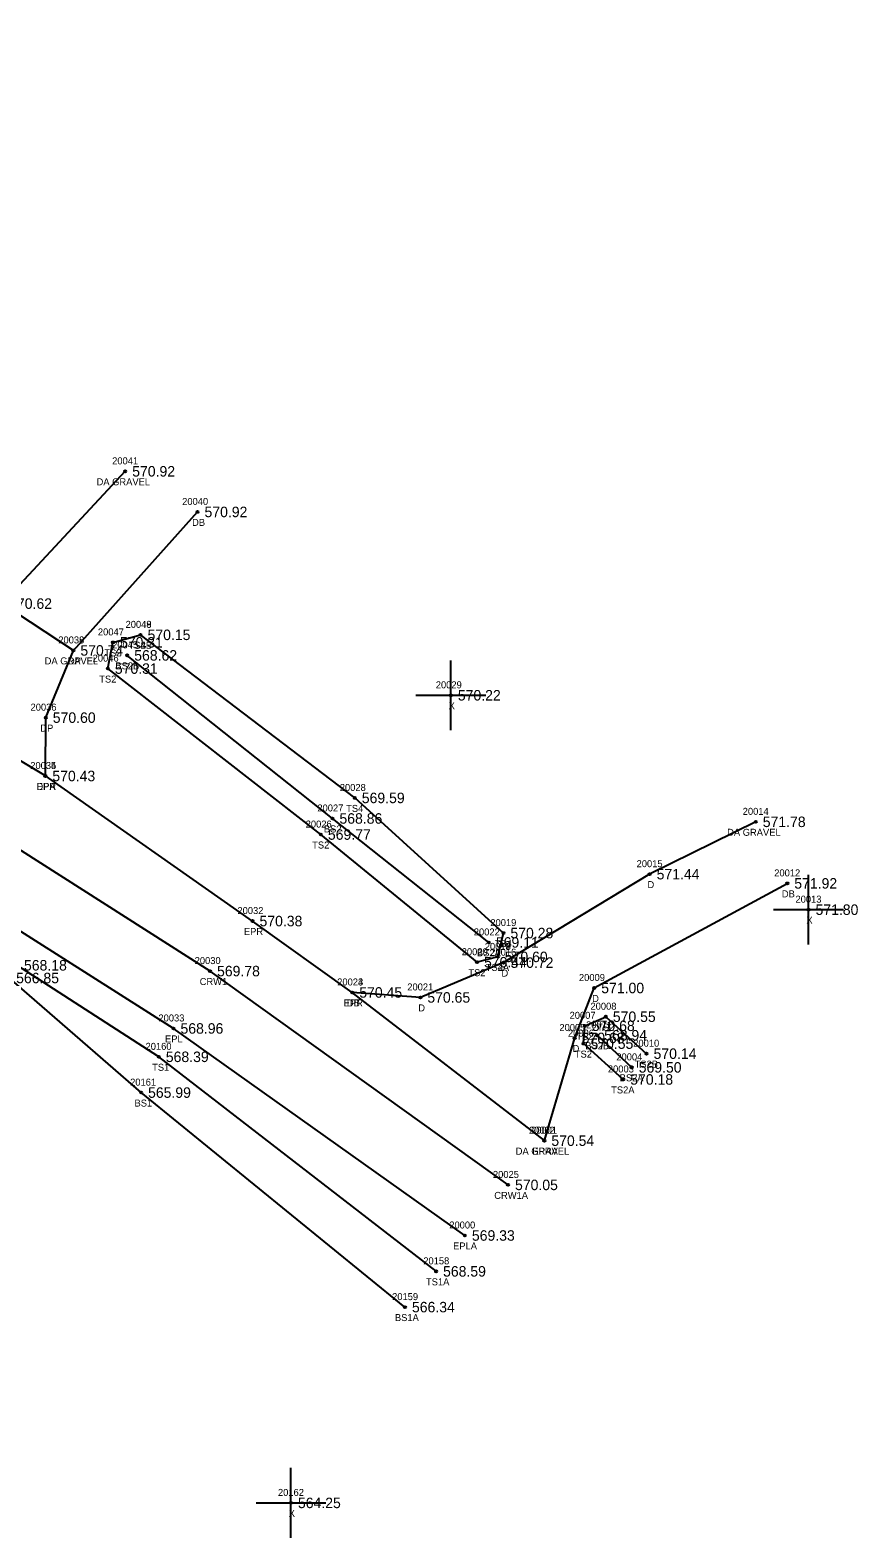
# Model space of a CAD drawing. Extents: x 1530159 to 1531652, y 877045 to 877724.
# Drawn here: x 1531533 to 1531651.5, y 877077 to 877292.8 of the extents above; entities that cross this region are included whole.
import ezdxf

# ---------------------------------------------------------------- set-up
doc = ezdxf.new("R2010")
doc.units = 0
for name, color, linetype in [('RD_DTM_BkLn1', 7, 'Continuous'), ('RD_DTM_BkLn2', 7, 'Continuous'), ('RD_DTM_BkLn_txCode', 7, 'Continuous'), ('RD_EX_Driveway', 7, 'Continuous'), ('RD_EX_Driveway_txCode', 7, 'Continuous'), ('RD_EX_Misc', 7, 'Continuous'), ('RD_EX_Misc_txCode', 7, 'Continuous'), ('RD_EX_Road', 7, 'Continuous'), ('RD_EX_Road_txCode', 7, 'Continuous'), ('RD_EX_TX_Driveway_ELEV', 7, 'Continuous'), ('RD_EX_TX_Misc_ELEV', 7, 'Continuous'), ('RD_EX_TX_Road_ELEV', 7, 'Continuous'), ('RD_HC_Survey_ELEV', 7, 'Continuous'), ('RD_HC_Survey_txCode', 7, 'Continuous'), ('RD_SMD_Locator', 7, 'Continuous')]:
    doc.layers.add(name, color=color, linetype=linetype)

msp = doc.modelspace()

# ---------------------------------------------------------------- linework, layer by layer
at = {"layer": 'RD_DTM_BkLn1'}
msp.add_lwpolyline([(1531601.44, 877127.51), (1531558.79, 877158.11), (1531516.37, 877185.16), (1531470.77, 877211.58), (1531426.8, 877229.22), (1531379.86, 877245.66), (1531330.99, 877260.09), (1531284.24, 877270.97), (1531236.44, 877276.73), (1531185.96, 877281.19), (1531132.29, 877281.48), (1531081.11, 877280.78), (1531028.25, 877278.4), (1530978.85, 877276.13), (1530941.18, 877274.78)], dxfattribs=at)
at = {"layer": 'RD_DTM_BkLn2'}
msp.add_line((1531619.14, 877144.33), (1531614.2, 877148.92), dxfattribs=at)
for points in [[(1531591.14, 877115.14), (1531551.46, 877145.84), (1531531.16, 877158.94), (1531508.8, 877174.74), (1531464.68, 877197.55), (1531424.35, 877215.57), (1531374.79, 877230.73), (1531373.87, 877227.7), (1531395.15, 877220.58)], [(1531586.69, 877110.02), (1531548.92, 877140.72), (1531530.04, 877157.12), (1531505.77, 877171.31), (1531462.4, 877192.61), (1531421.83, 877211.77), (1531413.77, 877214.99), (1531376.63, 877228.45)], [(1531599.98, 877160.14), (1531597, 877159.38), (1531574.66, 877177.65), (1531544.17, 877201.4), (1531544.9, 877205.15), (1531548.85, 877206.23)], [(1531599.98, 877160.14), (1531600.78, 877163.55), (1531579.51, 877182.89), (1531548.85, 877206.23)], [(1531598.7, 877162.21), (1531576.31, 877179.95), (1531546.94, 877203.29)], [(1531617.93, 877142.6), (1531612.24, 877147.73), (1531612.44, 877150.28), (1531615.44, 877151.58), (1531621.27, 877146.29)]]:
    msp.add_lwpolyline(points, dxfattribs=at)
at = {"layer": 'RD_EX_Driveway'}
for p, q in [((1531546.65, 877229.63), (1531529.04, 877210.7)), ((1531539.23, 877204), (1531557, 877223.82))]:
    msp.add_line(p, q, dxfattribs=at)
for points in [[(1531535.22, 877186.03), (1531535.28, 877194.38), (1531539.23, 877204), (1531529.04, 877210.7), (1531521.57, 877203.29), (1531511.53, 877200.27)], [(1531636.9, 877179.47), (1531621.71, 877171.98), (1531600.8, 877159.32), (1531588.89, 877154.34), (1531579.15, 877155.05)], [(1531606.64, 877133.84), (1531610.98, 877148.54), (1531613.78, 877155.69), (1531641.41, 877170.66)]]:
    msp.add_lwpolyline(points, dxfattribs=at)
at = {"layer": 'RD_EX_Misc'}
for p, q in [((1531593.26, 877192.58), (1531593.26, 877202.58)), ((1531588.26, 877197.58), (1531598.26, 877197.58)), ((1531644.45, 877161.9), (1531644.45, 877171.9)), ((1531639.45, 877166.9), (1531649.45, 877166.9)), ((1531570.37, 877077), (1531570.37, 877087)), ((1531565.37, 877082), (1531575.37, 877082))]:
    msp.add_line(p, q, dxfattribs=at)
at = {"layer": 'RD_EX_Road'}
for points in [[(1531606.64, 877133.84), (1531579.15, 877155.05), (1531564.87, 877165.27), (1531535.22, 877186.03), (1531511.53, 877200.27), (1531474.57, 877218.9), (1531430.45, 877239.35), (1531404.48, 877249.38), (1531382.32, 877256.43), (1531333.23, 877270.71), (1531303.67, 877277.44), (1531276.52, 877282.71), (1531237.32, 877287.2), (1531185.8, 877290.94), (1531132.61, 877292.77), (1531081.11, 877292.38), (1531038.69, 877288.67), (1530976.42, 877285.45), (1530941.06, 877284.26)], [(1531595.27, 877120.27), (1531553.56, 877149.9), (1531509.97, 877177.57), (1531465.94, 877201.73), (1531423.65, 877222), (1531376.09, 877237.68), (1531328.84, 877252.31), (1531282.81, 877261.85), (1531235.7, 877268.49), (1531185.47, 877272.84), (1531132.72, 877273.12), (1531080.2, 877271.87), (1531029.21, 877269.53), (1530978.47, 877268.32), (1530945.95, 877265.93), (1530941.45, 877262.44)]]:
    msp.add_lwpolyline(points, dxfattribs=at)
at = {"layer": 'RD_SMD_Locator'}
for centre in [(1531546.65, 877229.63), (1531557, 877223.82), (1531544.9, 877205.15), (1531548.85, 877206.23), (1531548.85, 877206.23), (1531539.23, 877204), (1531539.23, 877204), (1531546.94, 877203.29), (1531544.17, 877201.4), (1531593.26, 877197.58), (1531535.28, 877194.38), (1531535.22, 877186.03), (1531535.22, 877186.03), (1531579.51, 877182.89), (1531576.31, 877179.95), (1531636.9, 877179.47), (1531574.66, 877177.65), (1531621.71, 877171.98), (1531641.41, 877170.66), (1531644.45, 877166.9), (1531564.87, 877165.27), (1531600.78, 877163.55), (1531598.7, 877162.21), (1531597, 877159.38), (1531599.98, 877160.14), (1531599.98, 877160.14), (1531600.8, 877159.32), (1531558.79, 877158.11), (1531579.15, 877155.05), (1531579.15, 877155.05), (1531613.78, 877155.69), (1531588.89, 877154.34), (1531615.44, 877151.58), (1531553.56, 877149.9), (1531610.98, 877148.54), (1531612.44, 877150.28), (1531614.2, 877148.92), (1531612.24, 877147.73), (1531621.27, 877146.29), (1531551.46, 877145.84), (1531619.14, 877144.33), (1531617.93, 877142.6), (1531548.92, 877140.72), (1531606.64, 877133.84), (1531606.64, 877133.84), (1531601.44, 877127.51), (1531595.27, 877120.27), (1531591.14, 877115.14), (1531586.69, 877110.02), (1531570.37, 877082)]:
    msp.add_circle(centre, 0.15, dxfattribs=at)

# ---------------------------------------------------------------- texts
at = {"layer": 'RD_DTM_BkLn_txCode'}
for s, p in [('20047', (1531542.74, 877206.15)), ('20048', (1531546.7, 877207.23)), ('20049', (1531546.7, 877207.23)), ('20045', (1531544.78, 877204.29)), ('TS2B', (1531547.14, 877204.23)), ('TS4B', (1531547.14, 877204.23)), ('20046', (1531541.99, 877202.4)), ('TS2', (1531543.66, 877203.15)), ('TS2', (1531542.93, 877199.4)), ('BS2B', (1531545.24, 877201.29)), ('20028', (1531577.36, 877183.89)), ('20027', (1531574.15, 877180.95)), ('TS4', (1531578.27, 877180.89)), ('20026', (1531572.48, 877178.65)), ('BS2', (1531575.08, 877177.95)), ('TS2', (1531573.41, 877175.65)), ('20022', (1531596.54, 877163.21)), ('20019', (1531598.91, 877164.55)), ('20017', (1531598.11, 877161.14)), ('20018', (1531598.11, 877161.14)), ('TS4', (1531599.54, 877161.55)), ('20020', (1531594.81, 877160.38)), ('BS2A', (1531596.98, 877160.21)), ('TS2', (1531595.76, 877157.38)), ('TS2A', (1531598.25, 877158.14)), ('TS4A', (1531598.25, 877158.14)), ('20008', (1531613.24, 877152.58)), ('20007', (1531610.25, 877151.28)), ('20011', (1531612.61, 877149.92)), ('20006', (1531610.02, 877148.73)), ('TS2', (1531611.2, 877148.28)), ('TS2', (1531614.2, 877149.58)), ('20160', (1531549.56, 877146.84)), ('TS2', (1531611, 877145.73)), ('BS2B', (1531612.5, 877146.92)), ('20010', (1531619.36, 877147.29)), ('TS1', (1531550.5, 877143.84)), ('20003', (1531615.73, 877143.6)), ('20004', (1531616.94, 877145.33)), ('TS2B', (1531619.56, 877144.29)), ('20161', (1531547.35, 877141.72)), ('BS2A', (1531617.42, 877142.33)), ('TS2A', (1531616.2, 877140.6)), ('BS1', (1531547.98, 877138.72)), ('20158', (1531589.31, 877116.14)), ('TS1A', (1531589.7, 877113.14)), ('20159', (1531584.85, 877111.02)), ('BS1A', (1531585.25, 877108.02))]:
    msp.add_text(s, height=1, dxfattribs=at).set_placement(p)
at = {"layer": 'RD_EX_Driveway_txCode'}
for s, p in [('20041', (1531544.78, 877230.63)), ('DA GRAVEL', (1531542.55, 877227.63)), ('20040', (1531554.8, 877224.82)), ('DB', (1531556.22, 877221.82)), ('20038', (1531537.07, 877205)), ('20039', (1531537.07, 877205)), ('DA GRAVEL', (1531535.12, 877202)), ('DP', (1531538.45, 877202)), ('20036', (1531533.1, 877195.38)), ('DP', (1531534.5, 877192.38)), ('20035', (1531533.06, 877187.03)), ('DPA', (1531533.95, 877184.03)), ('20014', (1531635.03, 877180.47)), ('DA GRAVEL', (1531632.8, 877177.47)), ('20015', (1531619.84, 877172.98)), ('20012', (1531639.54, 877171.66)), ('D', (1531621.4, 877169.98)), ('DB', (1531640.63, 877168.66)), ('20016', (1531598.9, 877160.32)), ('D', (1531600.5, 877157.32)), ('20009', (1531611.59, 877156.69)), ('20023', (1531576.99, 877156.05)), ('20021', (1531587.02, 877155.34)), ('DB', (1531578.37, 877153.05)), ('D', (1531588.59, 877152.34)), ('D', (1531613.48, 877153.69)), ('20005', (1531608.79, 877149.54)), ('D', (1531610.68, 877146.54)), ('20002', (1531604.44, 877134.84)), ('DA GRAVEL', (1531602.54, 877131.84))]:
    msp.add_text(s, height=1, dxfattribs=at).set_placement(p)
at = {"layer": 'RD_EX_Misc_txCode'}
for s, p in [('20029', (1531591.1, 877198.58)), ('X', (1531592.94, 877195.58)), ('20013', (1531642.58, 877167.9)), ('X', (1531644.14, 877164.9)), ('20162', (1531568.51, 877083)), ('X', (1531570.05, 877080))]:
    msp.add_text(s, height=1, dxfattribs=at).set_placement(p)
at = {"layer": 'RD_EX_Road_txCode'}
for s, p in [('20034', (1531533.06, 877187.03)), ('EPR', (1531533.99, 877184.03)), ('20032', (1531562.71, 877166.27)), ('EPR', (1531563.64, 877163.27)), ('20024', (1531576.99, 877156.05)), ('EPR', (1531577.92, 877153.05)), ('20033', (1531551.4, 877150.9)), ('EPL', (1531552.35, 877147.9)), ('20001', (1531604.73, 877134.84)), ('EPRA', (1531604.92, 877131.84)), ('20000', (1531593.03, 877121.27)), ('EPLA', (1531593.58, 877118.27))]:
    msp.add_text(s, height=1, dxfattribs=at).set_placement(p)
at = {"layer": 'RD_EX_TX_Driveway_ELEV'}
for s, p in [('570.92', (1531547.65, 877228.88)), ('570.92', (1531558, 877223.07)), ('570.62', (1531530.04, 877209.95)), ('570.62', (1531530.04, 877209.95)), ('570.74', (1531540.23, 877203.25)), ('570.74', (1531540.23, 877203.25)), ('570.60', (1531536.28, 877193.63)), ('570.43', (1531536.22, 877185.28)), ('571.78', (1531637.9, 877178.72)), ('571.44', (1531622.71, 877171.23)), ('571.92', (1531642.41, 877169.91)), ('570.72', (1531601.8, 877158.57)), ('570.45', (1531580.15, 877154.3)), ('570.65', (1531589.89, 877153.59)), ('571.00', (1531614.78, 877154.94)), ('570.68', (1531611.98, 877147.79)), ('570.54', (1531607.64, 877133.09))]:
    msp.add_text(s, height=1.5, dxfattribs=at).set_placement(p)
at = {"layer": 'RD_EX_TX_Misc_ELEV'}
for s, p in [('570.15', (1531549.85, 877205.48)), ('570.15', (1531549.85, 877205.48)), ('570.31', (1531545.9, 877204.4)), ('568.62', (1531547.94, 877202.54)), ('570.31', (1531545.17, 877200.65)), ('570.22', (1531594.26, 877196.83)), ('569.59', (1531580.51, 877182.14)), ('568.86', (1531577.31, 877179.2)), ('569.77', (1531575.66, 877176.9)), ('571.80', (1531645.45, 877166.15)), ('570.28', (1531601.78, 877162.8)), ('569.11', (1531599.7, 877161.46)), ('568.18', (1531532.16, 877158.19)), ('570.44', (1531598, 877158.63)), ('570.60', (1531600.98, 877159.39)), ('570.60', (1531600.98, 877159.39)), ('566.85', (1531531.04, 877156.37)), ('570.68', (1531613.44, 877149.53)), ('570.55', (1531616.44, 877150.83)), ('568.94', (1531615.2, 877148.17)), ('568.39', (1531552.46, 877145.09)), ('570.55', (1531613.24, 877146.98)), ('570.14', (1531622.27, 877145.54)), ('569.50', (1531620.14, 877143.58)), ('570.18', (1531618.93, 877141.85)), ('565.99', (1531549.92, 877139.97)), ('568.59', (1531592.14, 877114.39)), ('566.34', (1531587.69, 877109.27)), ('564.25', (1531571.37, 877081.25))]:
    msp.add_text(s, height=1.5, dxfattribs=at).set_placement(p)
at = {"layer": 'RD_EX_TX_Road_ELEV'}
for s, p in [('570.43', (1531536.22, 877185.28)), ('570.38', (1531565.87, 877164.52)), ('570.45', (1531580.15, 877154.3)), ('568.96', (1531554.56, 877149.15)), ('570.54', (1531607.64, 877133.09)), ('569.33', (1531596.27, 877119.52))]:
    msp.add_text(s, height=1.5, dxfattribs=at).set_placement(p)
at = {"layer": 'RD_HC_Survey_ELEV'}
for s, p in [('569.78', (1531559.79, 877157.36)), ('570.05', (1531602.44, 877126.76))]:
    msp.add_text(s, height=1.5, dxfattribs=at).set_placement(p)
at = {"layer": 'RD_HC_Survey_txCode'}
for s, p in [('20030', (1531556.59, 877159.11)), ('CRW1', (1531557.31, 877156.11)), ('20025', (1531599.28, 877128.51)), ('CRW1A', (1531599.47, 877125.51))]:
    msp.add_text(s, height=1, dxfattribs=at).set_placement(p)

doc.saveas('drawing.dxf')
